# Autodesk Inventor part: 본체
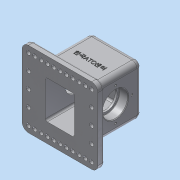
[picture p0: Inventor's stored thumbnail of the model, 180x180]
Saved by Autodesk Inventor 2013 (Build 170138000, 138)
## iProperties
Created: 2018-11
Part Number: 본체
Material: 알루미늄 6061
Document SubType Name: Modeling
Designer: dgall
Density: 2.71 g/cm^3
Mass: 1020.76 g
Surface Area: 777.082 cm^2
Volume: 376.663 cm^3
Author: dgall
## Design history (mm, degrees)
sketch "스케치1"
  geometry: L1 (-40, 45)-(40, 45); L2 (40, 45)-(40, -45); L3 (40, -45)-(-40, -45); L4 (-40, -45)-(-40, 45); 3 further points
  constraints: 8 end point, 2 midpoint, 2 parallel, 1 horizontal, 1 horizontal alignment, 1 perpendicular, 1 vertical alignment
  dimensions: "d0" = 80 distance of L1.start L1.end; "d2" = 90 distance of L1.end L2.end
extrude "돌출1" new body sketch "스케치1" stored distance "d3" = 80; taper "d4" = 0 deg
sketch "스케치2"
  geometry: L1 (-20, 20)-(100, 20); L2 (100, 20)-(100, -100); L3 (100, -100)-(-20, -100); L4 (-20, -100)-(-20, 20); 8 further points
  constraints: 8 end point, 5 vertical alignment, 2 midpoint, 2 parallel, 1 horizontal, 1 horizontal alignment, 1 perpendicular
  dimensions: "d5" = 120 distance of L1.start L1.end; "d7" = 120 distance of L1.end L2.end; "d8" = 10 horizontal distance of L1.start point (-10, 10); "d9" = 10 horizontal distance of L1.start point (-10, 10); "d10" = 25 distance of point (-10, -15) point (-10, 10); "d11" = 25 distance of point (-10, -15) point (-10, -40); "d12" = 25 distance of point (-10, -40) point (-10, -65); "d13" = 25 distance of point (-10, -65) point (-10, -90)
extrude "돌출2" join sketch "스케치2" distance "d14" = 10; taper "d15" = 0 deg
hole "구멍1" sketch "스케치2" diameter "d16" = 6.6; stored, may be unused: countersink angle "d20" = 90 deg, drill point angle "d22" = 118 deg; dims "d17" = 6, "d18" = 4, "d19" = 2, "d21" = 8
sketch "스케치3"
  geometry: L1 (37, -30)-(83, -30); L2 (83, -30)-(83, -90); L3 (83, -90)-(37, -90); L4 (37, -90)-(37, -30); 3 further points
  constraints: 8 end point, 2 midpoint, 2 parallel, 1 horizontal, 1 horizontal alignment, 1 perpendicular, 1 vertical alignment
  dimensions: "d23" = 60 distance of L1.end L2.end; "d25" = 46 distance of L1.start L1.end
extrude "돌출3" cut sketch "스케치3" distance "d26" = 80; taper "d27" = 0 deg
sketch "스케치4"
  geometry: L1 (0, -120)-(0, 0) reference; 11 further points
  constraints: 9 horizontal alignment
  dimensions: "d28" = 20 distance from line of L1 point (20, -110); "d29" = 10 vertical distance of L1.start point (20, -110); "d30" = 10 distance of point (30, -110) point (20, -110); "d31" = 10 distance of point (30, -110) point (40, -110); "d32" = 10 distance of point (40, -110) point (50, -110); "d33" = 10 distance of point (50, -110) point (60, -110); "d34" = 10 distance of point (60, -110) point (70, -110); "d35" = 10 distance of point (70, -110) point (80, -110); "d36" = 10 distance of point (80, -110) point (90, -110); "d37" = 10 distance of point (100, -110) point (90, -110); "d38" = 10 distance of point (100, -110) point (110, -110)
hole "구멍2" sketch "스케치4" at (20, -110), (30, -110), (40, -110), (50, -110), (60, -110), (70, -110), (80, -110), (90, -110), (100, -110), (110, -110) diameter "d39" = 6.6; stored, may be unused: countersink angle "d43" = 90 deg, drill point angle "d45" = 118 deg; dims "d40" = 6, "d41" = 4, "d42" = 2, "d44" = 8
node "작업 평면1"
node "작업 평면2"
sketch "스케치5"
  geometry: L1 (-20, -90)-(100, -90) reference; C1 r 20 at (40, -42); 1 further point
  constraints: 1 centre point, 1 vertical alignment
  dimensions: "d46" = 40 diameter of C1; "d47" = 48 distance from line of L1 C1.centre
extrude "돌출4" cut sketch "스케치5" distance "d48" = 14; taper "d49" = 0 deg
sketch "스케치6"
  geometry: C1 r 20 at (0, 0) reference; C2 r 16.5 at (0, 0); 1 further point
  constraints: 1 centre point, 1 coincident
  dimensions: "d50" = 33 diameter of C2
extrude "돌출5" cut sketch "스케치6" distance "d51" = 3; taper "d52" = 0 deg
fillet "모깎기1" dims "d53" = 8
fillet "모깎기2" dims "d54" = 8
fillet "모깎기3" dims "d55" = 3
fillet "모깎기4" dims "d56" = 10
fillet "모깎기5" dims "d57" = 3
node "작업 평면3"
sketch "스케치7"
  geometry: C1 r 7.5 at (0, 0); 1 further point
  constraints: 1 centre point, 1 coincident
  dimensions: "d59" = 15 diameter of C1
extrude "돌출6" join sketch "스케치7" stored distance "d60" = 3; taper "d61" = 0 deg
hole "구멍3" diameter "d64" = 4.917; stored, may be unused: countersink angle "d68" = 90 deg, drill point angle "d70" = 118 deg; dims "d65" = 6, "d66" = 4, "d67" = 2, "d69" = 8, "d93" = 10, "d94" = 10
fillet "모깎기6" dims "d71" = 3
fillet "모깎기7" dims "d72" = 3
fillet "모깎기8" dims "d73" = 0.6
chamfer "모따기1" distance "d74" = 1; stored, may be unused: second distance "d75" = 2, angle "d76" = 45 deg
sketch "스케치8"
  geometry: C1 r 16.5 at (32, -34) reference; 2 further points
  constraints: 1 vertical alignment
  dimensions: "d85" = 26 distance of C1.centre point (32, -8)
hole "구멍4" sketch "스케치8" at (32, -8) diameter "d78" = 3.242; stored, may be unused: countersink angle "d82" = 90 deg, drill point angle "d84" = 118 deg; dims "d79" = 8, "d80" = 4, "d81" = 2, "d83" = 10
fillet "모깎기9" dims "d89" = 3
sketch "스케치9"
  geometry: L1 (-50, -45)-(50, -45) reference; 2 further points
  constraints: 1 vertical alignment, 1 other
  dimensions: "d90" = 48 distance from line of L1 point (0, 3)
feature "엠보싱1" sketch "스케치9" dims "d19" = 2, "d91" = 0.5, "d92" = 0
node "솔리드1"
mirror "대칭1"
mirror "대칭2"
mirror "대칭3"
pattern_circular "원형 패턴1" dims angle "d87" = 360 deg
mirror "대칭4"
